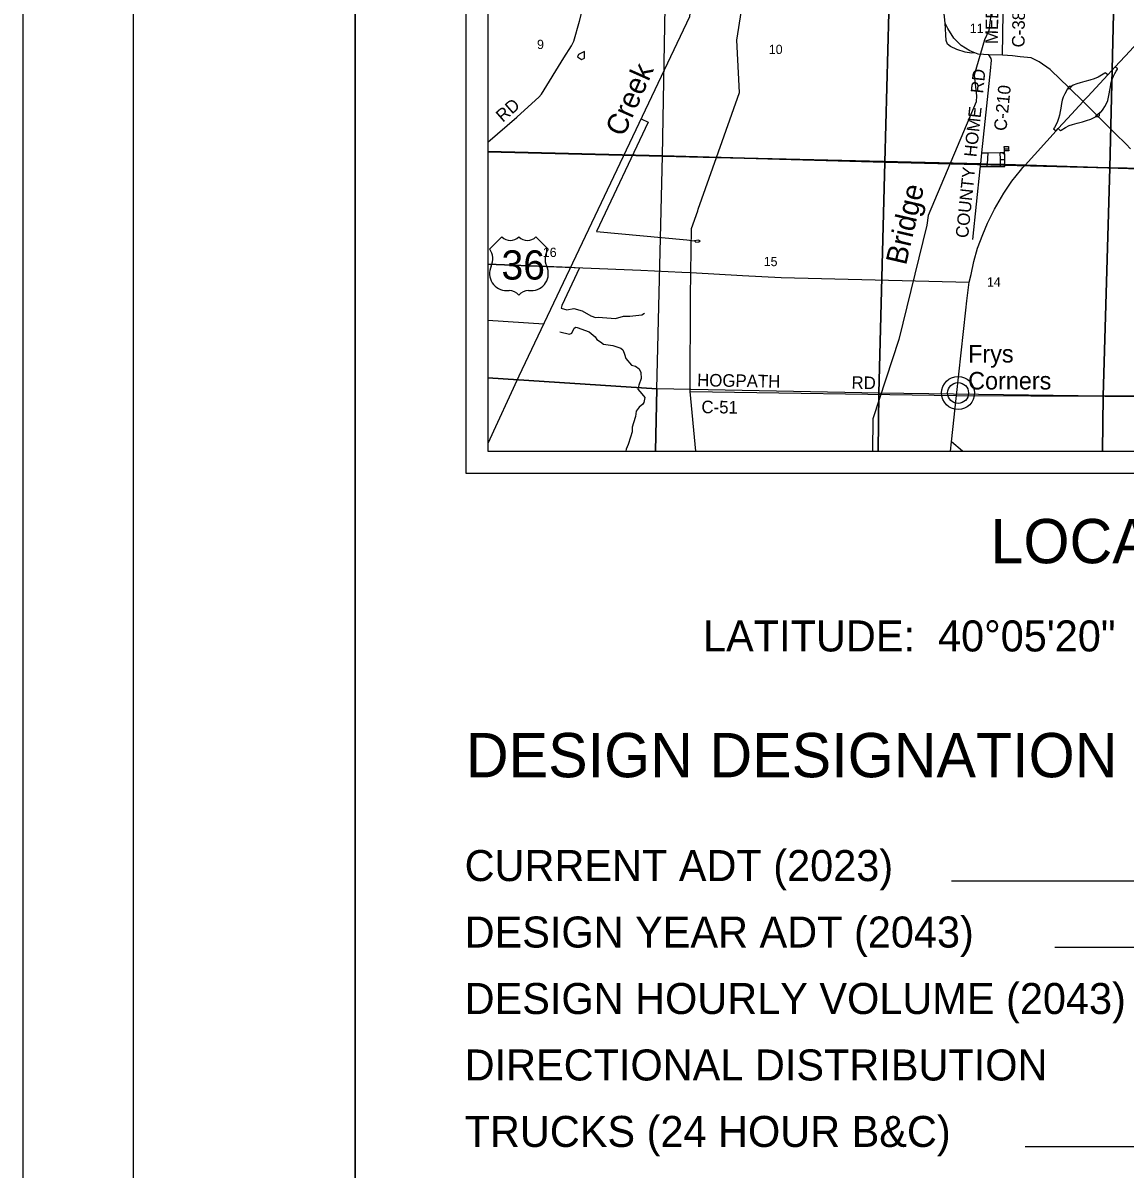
# Model space of a CAD drawing. Extents: x 0 to 1391, y -24 to 440.
# Drawn here: x 0 to 99.5, y 217.2 to 320.7 of the extents above; entities that cross this region are included whole.
import ezdxf

# ---------------------------------------------------------------- set-up
doc = ezdxf.new("R2010")
doc.units = 0
for name, color, linetype in [('GM_X_County_Road', 7, 'Continuous'), ('GM_X_County_Road_Text', 7, 'Continuous'), ('GM_X_County_ROW', 7, 'Continuous'), ('GM_X_Interchange_Ramps', 7, 'Continuous'), ('GM_X_Minor_Lake', 7, 'Continuous'), ('GM_X_Minor_River', 7, 'Continuous'), ('GM_X_Minor_River_Text', 7, 'Continuous'), ('GM_X_Section', 7, 'Continuous'), ('GM_X_Section_Text', 7, 'Continuous'), ('GM_X_State_Route', 7, 'Continuous'), ('GM_X_Township', 7, 'Continuous'), ('GM_X_Township_Road', 7, 'Continuous'), ('GM_X_Unincorporated', 7, 'Continuous'), ('GM_X_Unincorporated_Location', 7, 'Continuous'), ('GM_X_Unincorporated_Text', 7, 'Continuous'), ('GM_X_US_Location', 7, 'Continuous'), ('GM_X_US_Route', 7, 'Continuous'), ('GM_X_US_Shield', 7, 'Continuous'), ('SH_Border', 7, 'Continuous'), ('SH_Cut_Line', 7, 'Continuous'), ('SH_Data', 7, 'Continuous'), ('SH_Text', 7, 'Continuous')]:
    doc.layers.add(name, color=color, linetype=linetype)

msp = doc.modelspace()

# ---------------------------------------------------------------- linework, layer by layer
at = {"layer": 'GM_X_County_Road'}
for points in [[(88.47, 317.76), (88.74, 334.83)], [(42, 309.9), (44.61, 312.15), (45.97, 313.38), (46.59, 313.95), (46.82, 314.22), (48.86, 317.5), (49.54, 318.6), (49.74, 319), (50.25, 320.81), (51.95, 327.54), (51.98, 327.55), (54.25, 326.78), (54.99, 326.53), (55.64, 326.3), (56.21, 326.05), (56.72, 325.82), (57.64, 325.35), (58.2, 325.1), (58.66, 324.96), (65.3, 324.49)], [(85.97, 317.97), (85.65, 317.92), (85.1, 318.01), (84.33, 318.26), (83.78, 318.52), (83.51, 318.75), (83.39, 319.07), (83.29, 320.65)], [(86.46, 307.5), (86.48, 307.69), (86.5, 307.93), (86.6, 308.94), (87.06, 313.18), (87.37, 316.33), (87.48, 317.29), (87.45, 317.45), (87.23, 317.79)], [(88.41, 308.95), (88.47, 308.95), (88.65, 308.95), (88.64, 309.11), (88.63, 309.3), (88.62, 309.49), (89.01, 309.49), (89.02, 309.3), (89.03, 309.12), (88.64, 309.11)], [(86.6, 308.94), (87.18, 308.93), (88.26, 308.95), (88.41, 308.95)], [(87.09, 307.7), (87.09, 307.7), (88.28, 307.7), (88.68, 307.7), (88.68, 307.88), (88.67, 308.34), (88.66, 308.79), (88.65, 308.95)], [(87.09, 307.7), (87.11, 307.92), (87.18, 308.93)], [(88.27, 308.33), (88.26, 308.95)], [(88.27, 308.32), (88.67, 308.34)], [(88.28, 307.7), (88.28, 307.89), (88.27, 308.32), (88.27, 308.33)], [(88.63, 309.3), (89.02, 309.3)], [(85.77, 301.1), (86.46, 307.5), (86.46, 307.5)], [(86.48, 307.69), (87.09, 307.7)], [(60.27, 287.39), (84.3, 287.01)], [(84.3, 287.01), (117.91, 286.87)]]:
    msp.add_lwpolyline(points, dxfattribs=at)
at = {"layer": 'GM_X_County_ROW'}
msp.add_lwpolyline([(88.47, 308.95), (88.66, 308.79)], dxfattribs=at)
at = {"layer": 'GM_X_Interchange_Ramps'}
for points in [[(97.13, 312.19), (97.23, 312.3), (97.21, 312.36), (97.21, 312.42), (97.22, 312.46), (97.25, 312.52), (97.3, 312.58), (97.33, 312.61), (97.39, 312.67), (97.56, 312.87), (97.72, 313.11), (97.86, 313.38), (97.97, 313.64), (98.04, 313.96), (98.21, 314.88), (98.25, 315.13), (98.32, 315.39), (98.41, 315.65), (98.49, 315.86), (98.6, 316.1), (98.72, 316.31), (98.84, 316.49), (98.84, 316.5), (98.64, 316.69)], [(97.97, 315.96), (97.74, 316.16), (97.7, 316.13), (97.39, 315.93), (97.11, 315.77), (96.74, 315.61), (96.35, 315.48), (95.89, 315.36), (95.48, 315.26), (95.19, 315.15), (94.86, 315.03), (94.72, 314.95), (94.71, 314.95), (94.61, 314.92), (94.55, 314.92), (94.49, 314.93), (94.41, 314.85)], [(94.41, 314.85), (94.38, 314.82), (94.32, 314.71), (94.31, 314.69), (94.26, 314.58), (94.09, 314.27), (93.94, 313.96), (93.86, 313.68), (93.8, 313.38), (93.74, 312.97), (93.68, 312.65), (93.62, 312.33), (93.53, 312.02), (93.44, 311.76), (93.31, 311.49), (93.15, 311.21), (93.07, 311.11), (93.3, 310.91)], [(94.54, 314.73), (94.51, 314.7), (94.49, 314.72), (94.48, 314.72), (94.46, 314.72), (94.44, 314.72), (94.42, 314.72), (94.39, 314.71), (94.35, 314.67), (94.31, 314.69)], [(94.71, 314.95), (94.71, 314.92), (94.67, 314.88), (94.63, 314.83), (94.54, 314.73)], [(96.98, 312.33), (97.1, 312.45), (97.21, 312.54), (97.31, 312.63), (97.33, 312.61)], [(93.48, 311.12), (93.7, 310.93), (93.76, 310.98), (94.14, 311.22), (94.49, 311.39), (94.79, 311.5), (95.2, 311.62), (95.68, 311.74), (96.06, 311.86), (96.43, 311.97), (96.74, 312.11), (96.86, 312.18), (96.9, 312.2), (96.9, 312.2), (96.96, 312.21), (97, 312.22), (97.04, 312.22), (97.08, 312.21), (97.11, 312.18), (97.13, 312.19)], [(96.9, 312.2), (96.89, 312.21), (96.96, 312.31), (96.98, 312.33)]]:
    msp.add_lwpolyline(points, dxfattribs=at)
at = {"layer": 'GM_X_Minor_Lake'}
for points in [[(50.09, 317.59), (50.45, 317.37), (50.72, 317.49), (50.73, 318.08)], [(50.73, 318.08), (50.16, 317.8), (50.09, 317.59)], [(61.15, 301), (60.97, 301.06), (60.64, 300.99)], [(60.64, 300.99), (60.76, 300.87), (61.04, 300.9), (61.15, 301)]]:
    msp.add_lwpolyline(points, dxfattribs=at)
at = {"layer": 'GM_X_Minor_River'}
for points in [[(78.24, 362.05), (76.85, 361.57), (76.41, 361.23), (76.12, 360.69), (76.05, 360.45), (76.12, 359.79), (76.13, 358.73), (75.89, 358.22), (75.39, 357.85), (71.51, 354.42), (64.52, 343.57), (64.16, 342.97), (63.77, 342), (63.45, 340.74), (63.36, 337.48), (63.34, 337.29), (63.14, 336.22), (61.05, 331.28), (60.21, 321.22), (44.79, 288.77), (42, 282.69)], [(91.49, 335.62), (90.68, 334.87), (90.43, 334.71), (89.98, 333.43), (88.43, 331.27), (88.39, 329.54), (88, 328.16), (87.83, 322.71), (87.51, 322.09), (87.22, 319.96), (86.85, 319.13), (85.91, 315.93), (86.12, 314.08), (86.1, 313.52), (81.75, 303.28), (81.62, 302.4), (79.11, 292.09), (76.76, 284.93), (76.72, 282)], [(55.83, 312), (56.46, 311.69), (51.8, 301.82), (59.95, 301.09), (60.64, 300.99)], [(49.46, 298.59), (42, 298.88)], [(49.47, 298.61), (50.27, 298.56), (48.67, 295.15), (48.61, 294.92), (49.12, 294.77), (49.76, 294.88), (50.5, 294.67), (51.3, 294.23), (51.7, 294.07), (51.94, 294.1), (53.5, 293.98), (54.25, 294.2), (54.81, 294.18), (55.9, 294.31), (56.14, 294.45)], [(47.03, 293.47), (42, 293.79)], [(48.5, 292.77), (49.37, 292.56), (49.56, 292.66), (49.78, 293.1), (49.94, 293.18), (50.06, 293.17), (51.15, 292.78), (51.67, 292.33), (51.84, 292.09), (52.15, 291.88), (52.44, 291.67), (53.27, 291.53), (53.99, 291.31), (54.17, 291.16), (54.29, 290.84), (54.32, 290.76), (54.46, 290.37), (54.96, 289.77), (55.33, 289.66), (55.65, 289.42), (55.8, 289.11), (55.82, 288.55), (55.61, 287.97), (55.54, 287.59), (55.9, 287.18), (56.16, 286.84), (56.06, 286.39), (55.97, 286.25), (55.64, 285.97), (55.38, 285.61), (55.32, 285.13), (55.29, 285.05), (55.01, 284.17), (55.02, 283.75), (54.86, 283.25), (54.67, 282.59), (54.49, 282.17), (54.45, 282)]]:
    msp.add_lwpolyline(points, dxfattribs=at)
at = {"layer": 'GM_X_Section'}
for p, q in [((42, 329.06), (42, 309.05)), ((42, 309.05), (42, 288.62)), ((57.14, 282), (77.24, 282)), ((77.24, 282), (97.49, 282)), ((97.49, 282), (117.84, 282))]:
    msp.add_line(p, q, dxfattribs=at)
for points in [[(42, 309.05), (57.75, 308.67), (58.13, 328.84), (42, 329.06)], [(42, 288.62), (57.26, 287.64), (57.75, 308.67), (42, 309.05)], [(42, 288.62), (42, 282), (57.14, 282)], [(57.14, 282), (57.26, 287.64), (42, 288.62)], [(77.24, 282), (77.3, 287.23), (57.26, 287.64), (57.14, 282)], [(97.49, 282), (97.54, 286.97), (77.3, 287.23), (77.24, 282)], [(117.84, 282), (117.95, 286.98), (97.54, 286.97), (97.49, 282)]]:
    msp.add_lwpolyline(points, dxfattribs=at)
for points in [[(58.13, 328.84), (78.38, 328.33), (77.83, 308.09), (57.75, 308.67)], [(78.38, 328.33), (98.65, 327.86), (98.17, 307.59), (77.83, 308.09)], [(98.65, 327.86), (118.78, 327.43), (118.78, 327.3), (118.36, 307.17), (98.17, 307.59)], [(77.83, 308.09), (77.3, 287.23), (57.26, 287.64), (57.75, 308.67)], [(77.83, 308.09), (98.17, 307.59), (97.54, 286.97), (77.3, 287.23)], [(118.36, 307.17), (117.95, 286.98), (97.54, 286.97), (98.17, 307.59)]]:
    msp.add_lwpolyline(points, close=True, dxfattribs=at)
at = {"layer": 'GM_X_State_Route'}
for points in [[(60.99, 303.83), (62.65, 308.52), (64.71, 314.37), (64.46, 319.1), (65.3, 324.49), (65.49, 325.42), (67.43, 328.71)], [(87.23, 317.79), (86.27, 317.85), (85.97, 317.97), (85.5, 318.15), (84.73, 318.61), (84.06, 319.27), (83.54, 320.16), (83.29, 320.65), (82.89, 324.39)], [(92.86, 316.37), (92.77, 316.45), (91.79, 317.14), (91.06, 317.5), (90.06, 317.61), (89.38, 317.7), (88.47, 317.76), (87.23, 317.79)], [(95.74, 313.56), (94.54, 314.73), (94.41, 314.85), (92.86, 316.37)], [(96.02, 313.29), (95.74, 313.56)], [(98.59, 310.75), (97.13, 312.19), (96.98, 312.33), (96.02, 313.29)], [(100.03, 309.29), (99.97, 309.36), (99.69, 309.66), (98.59, 310.75)], [(60.3, 295.91), (60.32, 298.14), (60.38, 302.1), (60.94, 303.68), (60.99, 303.83)], [(60.78, 282), (60.27, 287.39), (60.3, 295.86), (60.3, 295.91)]]:
    msp.add_lwpolyline(points, dxfattribs=at)
at = {"layer": 'GM_X_Township'}
for points in [[(42, 418), (42, 309.03), (62.65, 308.52), (86.5, 307.93), (87.11, 307.92), (88.28, 307.89), (90.61, 307.83), (101.69, 307.47), (106.1, 307.37), (107.84, 307.33), (118.35, 307.09), (129.3, 306.91), (139.34, 306.87), (147.15, 306.91), (149.29, 306.89), (154.34, 306.79), (154.36, 311.23)], [(42, 309.03), (42, 282), (117.81, 282)], [(117.81, 282), (117.91, 286.87), (118.02, 291.15), (118.35, 307.09), (107.84, 307.33), (106.1, 307.37), (101.69, 307.47), (90.61, 307.83), (88.68, 307.88), (88.28, 307.89), (87.11, 307.92), (86.5, 307.93), (62.65, 308.52), (42, 309.03)]]:
    msp.add_lwpolyline(points, dxfattribs=at)
at = {"layer": 'GM_X_Township_Road'}
msp.add_lwpolyline([(84.86, 282), (83.85, 282.84)], dxfattribs=at)
at = {"layer": 'GM_X_Unincorporated'}
for radius in [1.49, 0.943]:
    msp.add_circle((84.45, 287.25), radius, dxfattribs=at)
at = {"layer": 'GM_X_Unincorporated_Location'}
msp.add_line((84.45, 287.25), (84.45, 287.25), dxfattribs=at)
at = {"layer": 'GM_X_US_Route'}
for points in [[(95.79, 313.62), (96.18, 314.01), (97.97, 315.96), (98.64, 316.69), (99.97, 318.12), (101.56, 319.86), (103.11, 321.52), (103.95, 322.43), (105.18, 323.8), (106.35, 325.43), (106.84, 326.19), (107.51, 327.4), (107.52, 327.42)], [(85.46, 297.24), (85.62, 297.94), (85.87, 299.11), (86.22, 300.31), (86.68, 301.57), (87.1, 302.59), (87.75, 303.83), (88.59, 305.3), (89.32, 306.37), (90.08, 307.35), (90.29, 307.6), (90.5, 307.83), (93.3, 310.91), (93.48, 311.12), (94.33, 312.02), (95.74, 313.56), (95.79, 313.62)], [(42, 298.89), (45.01, 298.76), (50.57, 298.55), (55.79, 298.33), (59.52, 298.17), (60.32, 298.14)], [(60.32, 298.14), (60.32, 298.14), (64.98, 297.86), (68.48, 297.68), (85.46, 297.24)], [(85.14, 294.74), (85.14, 294.74), (85.23, 295.58), (85.46, 297.24)], [(83.76, 282), (83.85, 282.84), (84.3, 287.01), (85.14, 294.74)]]:
    msp.add_lwpolyline(points, dxfattribs=at)
at = {"layer": 'GM_X_US_Shield'}
for p, q in [((43.25, 301.34), (42.15, 300.24)), ((47.43, 300.24), (46.33, 301.34)), ((43.69, 296.5), (43.91, 296.5)), ((45.67, 296.5), (45.89, 296.5))]:
    msp.add_line(p, q, dxfattribs=at)
for centre, radius, start, end in [((44.02, 302.12), 1.1, 225.573, 314.427), ((45.56, 302.12), 1.1, 225.573, 314.427), ((40.89, 299.36), 1.54, 334.5471, 35.0009), ((48.69, 299.36), 1.54, 144.9991, 205.4529), ((43.68, 298.04), 1.54, 154.8319, 270.6383), ((45.91, 298.04), 1.54, 269.3617, 25.1681), ((43.91, 295.41), 1.1, 36.8699, 90), ((45.67, 295.41), 1.1, 90, 143.1301)]:
    msp.add_arc(centre, radius, start, end, dxfattribs=at)
at = {"layer": 'SH_Border'}
for points in [[(10, 430), (30, 430), (30, 10), (10, 10)], [(30, 430), (670, 430), (670, 10), (30, 10)]]:
    msp.add_lwpolyline(points, close=True, dxfattribs=at)
at = {"layer": 'SH_Cut_Line'}
msp.add_lwpolyline([(0, 0), (680, 0), (680, 440), (0, 440)], close=True, dxfattribs=at)
at = {"layer": 'SH_Data'}
for p, q in [((40, 420), (40, 280)), ((42, 418), (42, 282)), ((42, 282), (178, 282)), ((40, 280), (180, 280)), ((152.85, 243.19), (83.87, 243.19)), ((152.74, 237.19), (93.18, 237.19)), ((152.74, 219.19), (90.52, 219.19))]:
    msp.add_line(p, q, dxfattribs=at)

# ---------------------------------------------------------------- texts
at = {"layer": 'GM_X_County_Road_Text'}
for s, rotation, p in [('MEEKER', 88.9979, (88.04, 318.74)), ('C-380', 89.1739, (90.45, 318.44)), ('RD', 84.0939, (86.71, 314.26)), ('C-210', 84.2072, (88.81, 310.87)), ('RD', 41.2759, (43.33, 311.64)), ('HOME', 83.9323, (86.11, 308.51)), ('COUNTY', 84.0428, (85.35, 301.2)), ('HOGPATH', 358.9924, (60.88, 287.86)), ('RD', 359.0109, (74.82, 287.63)), ('C-51', 359.3129, (61.27, 285.43))]:
    msp.add_text(s, height=1.136, rotation=rotation, dxfattribs=at).set_placement(p)
at = {"layer": 'GM_X_Minor_River_Text'}
for s, height, rotation, p in [('Creek', 1.897, 66.0051, (54.25, 310.29)), ('Bridge', 1.898, 76.9787, (79.75, 298.72))]:
    msp.add_text(s, height=height, rotation=rotation, dxfattribs=at).set_placement(p)
at = {"layer": 'GM_X_Section_Text'}
for s, p in [('11', (85.51, 319.75)), ('9', (46.43, 318.3)), ('10', (67.36, 317.85)), ('16', (46.95, 299.53)), ('15', (66.9, 298.7)), ('14', (87.06, 296.86))]:
    msp.add_text(s, height=0.837, rotation=0, dxfattribs=at).set_placement(p)
at = {"layer": 'GM_X_Unincorporated_Text'}
for s, p in [('Frys', (85.36, 290)), ('Corners', (85.36, 287.57))]:
    msp.add_text(s, height=1.58, rotation=0, dxfattribs=at).set_placement(p)
at = {"layer": 'GM_X_US_Location'}
msp.add_text('36', height=0.00379, rotation=0, dxfattribs=at).set_placement((44.01, 298.01))
for s in ['0', '/']:
    msp.add_text(s, height=0.00379, dxfattribs=at).set_placement((44.79, 298.79))
at = {"layer": 'GM_X_US_Shield'}
msp.add_text('36', height=2.637, dxfattribs=at).set_placement((43.22, 297.49))
at = {"layer": 'SH_Data'}
msp.add_text('DESIGN DESIGNATION', height=4, dxfattribs=at).set_placement((40, 252.56))
at = {"layer": 'SH_Text'}
for s, height, p in [('LOCATION MAP', 4, (87.38, 271.88)), ('LATITUDE:  40°05\'20"     LONGITUDE:  84°36\'27"', 2.8, (61.42, 263.92)), ('CURRENT ADT (2023)', 2.8, (39.89, 243.19)), ('DESIGN YEAR ADT (2043)', 2.8, (39.89, 237.19)), ('DESIGN HOURLY VOLUME (2043)', 2.8, (39.89, 231.19)), ('DIRECTIONAL DISTRIBUTION', 2.8, (39.89, 225.19)), ('TRUCKS (24 HOUR B&C)', 2.8, (39.89, 219.19))]:
    msp.add_text(s, height=height, dxfattribs=at).set_placement(p)

doc.saveas('drawing.dxf')
